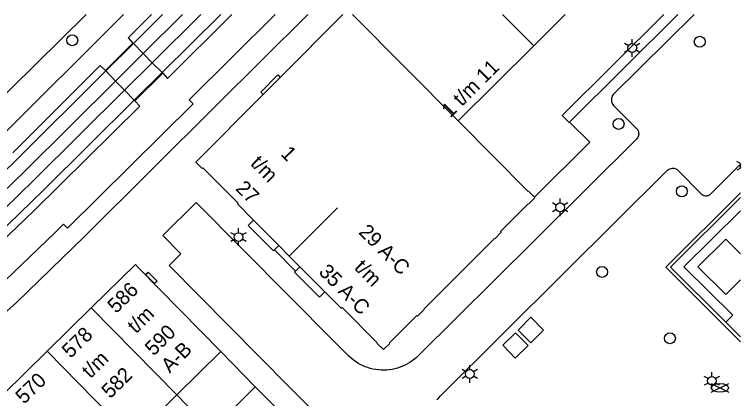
# Model space of a CAD drawing. Extents: x 122462 to 123306, y 485548 to 486417.
# Drawn here: x 123231.7 to 123306, y 486377.7 to 486417 of the extents above; entities that cross this region are included whole.
import ezdxf

# ---------------------------------------------------------------- set-up
doc = ezdxf.new("R2010")
doc.units = 0
for name, color, linetype in [('B-WE-IE-MEUBILAIR_WEGMEUBILAIR_VERKEERSBORD-S', 7, 'Continuous'), ('Level 1', 7, 'Continuous'), ('Level 17', 7, 'Continuous'), ('Level 19', 7, 'Continuous'), ('Level 21', 7, 'Continuous'), ('Level 30', 7, 'Continuous'), ('Level 31', 7, 'Continuous'), ('Level 37', 7, 'Continuous'), ('Level 4', 7, 'Continuous'), ('Level 40', 7, 'Continuous'), ('Level 42', 7, 'Continuous'), ('Level 50', 7, 'Continuous'), ('Level 52', 7, 'Continuous'), ('Level 53', 7, 'Continuous'), ('N-WE-AL-T25', 7, 'Continuous')]:
    doc.layers.add(name, color=color, linetype=linetype)

msp = doc.modelspace()

# ---------------------------------------------------------------- linework, layer by layer
at = {"layer": 'Level 1'}
for p, q in [((123284.843, 486413.759), (123288.06, 486416.958)), ((123277.113, 486406.073), (123284.843, 486413.759)), ((123258.889, 486410.532), (123257.139, 486408.777)), ((123256.156, 486395.927), (123258.75, 486393.326)), ((123258.75, 486393.326), (123259.824, 486392.249)), ((123259.824, 486392.249), (123260.91, 486391.16)), ((123260.91, 486391.16), (123263.474, 486388.589)), ((123239.549, 486386.962), (123235.039, 486382.526)), ((123235.039, 486382.526), (123230.529, 486378.09)), ((123248.312, 486378.054), (123252.82, 486382.489)), ((123256.34, 486378.88), (123251.87, 486374.438)), ((123243.802, 486373.618), (123248.312, 486378.054))]:
    msp.add_line(p, q, dxfattribs=at)
for points in [[(123265.299, 486416.958), (123258.889, 486410.532)], [(123257.139, 486408.777), (123250.249, 486401.87), (123250.899, 486401.219), (123250.964, 486401.284), (123254.589, 486397.659), (123254.509, 486397.579), (123256.156, 486395.927)], [(123284.912, 486398.276), (123284.299, 486398.889), (123284.269, 486398.859), (123277.113, 486406.073)], [(123263.474, 486388.589), (123265.14, 486386.92), (123265.219, 486386.999), (123268.834, 486383.364), (123268.799, 486383.329), (123269.479, 486382.679), (123270.122, 486383.325), (123270.087, 486383.36), (123272.893, 486386.175), (123272.964, 486386.105), (123273.627, 486386.77), (123273.592, 486386.806), (123280.821, 486394.057), (123280.856, 486394.022), (123281.528, 486394.696), (123281.457, 486394.766), (123284.264, 486397.583), (123284.3, 486397.547), (123284.969, 486398.219), (123284.912, 486398.276)], [(123252.82, 486382.489), (123244.419, 486391.01), (123244.059, 486391.4), (123239.549, 486386.962)], [(123260.294, 486374.764), (123260.37, 486374.84), (123256.34, 486378.88)]]:
    msp.add_lwpolyline(points, dxfattribs=at)
at = {"layer": 'Level 17'}
for p, q in [((123240.99, 486411.226), (123243.8, 486414.039)), ((123243.8, 486414.039), (123243.853, 486413.985)), ((123243.853, 486413.985), (123244.868, 486412.963)), ((123244.868, 486412.963), (123245.79, 486412.034)), ((123245.79, 486412.034), (123246.804, 486411.012)), ((123241.03, 486411.185), (123240.99, 486411.226)), ((123242.034, 486410.153), (123241.03, 486411.185)), ((123246.86, 486410.956), (123244.012, 486408.121)), ((123246.804, 486411.012), (123246.86, 486410.956)), ((123242.948, 486409.215), (123242.034, 486410.153)), ((123243.952, 486408.183), (123242.948, 486409.215)), ((123244.012, 486408.121), (123243.952, 486408.183)), ((123256.34, 486378.88), (123252.82, 486382.489))]:
    msp.add_line(p, q, dxfattribs=at)
for points in [[(123132.782, 486338.745), (123187.402, 486372.258), (123191.877, 486375.508), (123203.236, 486384.06), (123214.862, 486393.723), (123221.004, 486399.216), (123239.035, 486416.958)], [(123229.829, 486404.042), (123242.851, 486416.958)], [(123261.714, 486416.958), (123252.378, 486407.697), (123238.903, 486394.288), (123231.88, 486387.504), (123230.608, 486386.337)], [(123258.366, 486416.958), (123249.562, 486408.238), (123249.964, 486407.821), (123237.126, 486395.096), (123236.698, 486395.52), (123235.817, 486394.627), (123230.74, 486389.75)], [(123245.72, 486416.958), (123243.315, 486414.576), (123243.8, 486414.039)], [(123301.272, 486416.958), (123292.972, 486408.772), (123292.913, 486408.681), (123292.866, 486408.583), (123292.83, 486408.48), (123292.808, 486408.373), (123292.799, 486408.265), (123292.803, 486408.156), (123292.82, 486408.049), (123292.85, 486407.944), (123292.892, 486407.844), (123292.947, 486407.75), (123293.012, 486407.663), (123295.35, 486405.348), (123295.423, 486405.267), (123295.485, 486405.177), (123295.534, 486405.079), (123295.568, 486404.975), (123295.589, 486404.868), (123295.594, 486404.759), (123295.584, 486404.65), (123295.56, 486404.544), (123295.521, 486404.441), (123295.468, 486404.346), (123295.403, 486404.258), (123284.881, 486393.795), (123273.051, 486382.086), (123272.847, 486381.891), (123272.633, 486381.708), (123272.409, 486381.538), (123272.176, 486381.38), (123271.934, 486381.235), (123271.685, 486381.103), (123271.429, 486380.986), (123271.167, 486380.883), (123270.899, 486380.795), (123270.627, 486380.722), (123270.351, 486380.664), (123270.073, 486380.622), (123269.792, 486380.595), (123269.511, 486380.583), (123269.229, 486380.588), (123268.948, 486380.607), (123268.669, 486380.643), (123268.392, 486380.694), (123268.118, 486380.76), (123267.848, 486380.841), (123267.583, 486380.938), (123267.324, 486381.048), (123267.072, 486381.173), (123266.827, 486381.312), (123266.59, 486381.464), (123266.361, 486381.629), (123266.143, 486381.807), (123265.934, 486381.996), (123264.449, 486383.487), (123250.278, 486397.744), (123246.859, 486394.346), (123248.724, 486392.471), (123247.523, 486391.288), (123259.825, 486378.875), (123279.976, 486358.552)], [(123246.86, 486410.956), (123247.359, 486410.431), (123253.941, 486416.958)], [(123288.513, 486405.958), (123288.471, 486405.917), (123287.773, 486406.643), (123298.175, 486416.958)], [(123299.59, 486416.958), (123288.513, 486405.958)], [(123240.99, 486411.226), (123240.448, 486411.733), (123231.513, 486402.822)], [(123244.012, 486408.121), (123244.517, 486407.596), (123233.643, 486396.861), (123226.958, 486390.473)], [(123288.513, 486405.958), (123290.599, 486403.907), (123284.912, 486398.276)], [(123302.816, 486398.5), (123302.906, 486398.555), (123302.986, 486398.621), (123306.018, 486401.636)], [(123274.946, 486377.556), (123275.116, 486377.766), (123275.298, 486377.967), (123287.951, 486390.549), (123298.556, 486401.025), (123298.633, 486401.091), (123298.719, 486401.147), (123298.811, 486401.191), (123298.908, 486401.222), (123299.009, 486401.239), (123299.111, 486401.244), (123299.212, 486401.234), (123299.312, 486401.212), (123299.407, 486401.176), (123299.497, 486401.128), (123299.58, 486401.068), (123299.654, 486400.998), (123301.951, 486398.643), (123302.029, 486398.573), (123302.115, 486398.515), (123302.209, 486398.47), (123302.309, 486398.439), (123302.412, 486398.422), (123302.516, 486398.419), (123302.62, 486398.432), (123302.721, 486398.459), (123302.816, 486398.5)], [(123304.506, 486385.485), (123305.231, 486386.2), (123300.228, 486391.147), (123306.018, 486396.883)], [(123304.51, 486388.326), (123301.652, 486391.151), (123304.519, 486393.995), (123306.018, 486392.484)], [(123306.018, 486389.827), (123304.51, 486388.326)]]:
    msp.add_lwpolyline(points, dxfattribs=at)
at = {"layer": 'Level 19'}
msp.add_line((123251.87, 486374.438), (123248.312, 486378.054), dxfattribs=at)
at = {"layer": 'Level 21'}
for points in [[(123306.018, 486383.48), (123298.363, 486391.128), (123306.018, 486398.722)], [(123304.506, 486385.485), (123298.859, 486391.127), (123306.018, 486398.228)], [(123306.018, 486383.975), (123304.506, 486385.485)]]:
    msp.add_lwpolyline(points, dxfattribs=at)
at = {"layer": 'Level 30'}
for p, q in [((123258.75, 486393.326), (123258.295, 486392.874)), ((123260.455, 486390.707), (123260.91, 486391.16))]:
    msp.add_line(p, q, dxfattribs=at)
for points in [[(123257.139, 486408.777), (123256.891, 486409.024), (123258.641, 486410.779), (123258.889, 486410.532)], [(123258.295, 486392.874), (123258.192, 486392.771), (123255.599, 486395.371), (123256.156, 486395.927)], [(123263.474, 486388.589), (123262.917, 486388.034), (123260.353, 486390.605), (123260.455, 486390.707)]]:
    msp.add_lwpolyline(points, dxfattribs=at)
at = {"layer": 'Level 31'}
msp.add_line((123260.455, 486390.707), (123258.295, 486392.874), dxfattribs=at)
at = {"layer": 'Level 37'}
for p, q in [((123246.85, 486416.958), (123243.853, 486413.985)), ((123248.896, 486416.958), (123244.868, 486412.963)), ((123250.754, 486416.958), (123245.79, 486412.034)), ((123252.799, 486416.958), (123246.804, 486411.012)), ((123243.853, 486413.985), (123241.03, 486411.185)), ((123244.868, 486412.963), (123242.034, 486410.153)), ((123245.79, 486412.034), (123242.948, 486409.215)), ((123246.804, 486411.012), (123243.952, 486408.183))]:
    msp.add_line(p, q, dxfattribs=at)
for points in [[(123241.03, 486411.185), (123231.744, 486401.974), (123225.952, 486396.381), (123222.721, 486393.366), (123219.946, 486390.881), (123216.94, 486388.248), (123213.765, 486385.527), (123210.569, 486382.869), (123207.368, 486380.288), (123204.076, 486377.707), (123200.759, 486375.175), (123197.416, 486372.695), (123193.966, 486370.217), (123190.616, 486367.88), (123184.983, 486364.082), (123156.102, 486345.165)], [(123242.034, 486410.153), (123232.751, 486400.945), (123226.939, 486395.332), (123223.692, 486392.302), (123220.904, 486389.806), (123217.883, 486387.161), (123214.693, 486384.426), (123211.482, 486381.755), (123208.265, 486379.161), (123204.957, 486376.568), (123201.624, 486374.024), (123198.265, 486371.533), (123194.8, 486369.043), (123191.437, 486366.696), (123185.777, 486362.88), (123156.905, 486343.969)], [(123242.948, 486409.215), (123233.663, 486400.005), (123227.574, 486394.133), (123224.193, 486390.984), (123221.287, 486388.391), (123218.124, 486385.639), (123214.783, 486382.796), (123211.462, 486380.052), (123208.135, 486377.388), (123204.717, 486374.728), (123201.271, 486372.12), (123198.042, 486369.744), (123194.714, 486367.37), (123191.238, 486364.965), (123186.373, 486361.706), (123157.637, 486342.879)], [(123243.952, 486408.183), (123234.67, 486398.976), (123228.56, 486393.083), (123225.163, 486389.918), (123222.242, 486387.313), (123219.064, 486384.548), (123215.707, 486381.691), (123212.37, 486378.935), (123209.028, 486376.258), (123205.594, 486373.586), (123202.132, 486370.966), (123198.888, 486368.578), (123195.543, 486366.192), (123192.054, 486363.778), (123187.166, 486360.503), (123158.44, 486341.683)]]:
    msp.add_lwpolyline(points, dxfattribs=at)
at = {"layer": 'Level 4'}
for p, q in [((123277.113, 486406.073), (123266.308, 486416.958)), ((123284.843, 486413.759), (123281.664, 486416.958)), ((123248.312, 486378.054), (123239.549, 486386.962)), ((123243.802, 486373.618), (123235.039, 486382.526))]:
    msp.add_line(p, q, dxfattribs=at)
at = {"layer": 'Level 40'}
msp.add_lwpolyline([(123246.028, 486389.442), (123245.114, 486390.367), (123245.363, 486390.613), (123246.277, 486389.688), (123246.028, 486389.442)], dxfattribs=at)
at = {"layer": 'Level 42'}
for points in [[(123284.561, 486383.366), (123283.252, 486384.675), (123284.564, 486385.988), (123285.857, 486384.678), (123284.561, 486383.366)], [(123282.961, 486381.805), (123281.68, 486383.123), (123282.987, 486384.396), (123284.278, 486383.09), (123282.961, 486381.805)]]:
    msp.add_lwpolyline(points, dxfattribs=at)
at = {"layer": 'Level 50'}
for p, q in [((123294.939, 486413.986), (123294.939, 486414.436)), ((123294.549, 486413.761), (123294.159, 486413.986)), ((123295.718, 486413.986), (123295.328, 486413.761)), ((123294.549, 486413.311), (123294.159, 486413.086)), ((123294.939, 486412.636), (123294.939, 486413.086)), ((123295.718, 486413.086), (123295.328, 486413.311)), ((123306.018, 486401.704), (123305.638, 486401.923)), ((123306.018, 486401.266), (123306.018, 486401.679)), ((123306.018, 486401.242), (123305.638, 486401.023)), ((123287.55, 486397.683), (123287.55, 486398.133)), ((123287.16, 486397.458), (123286.77, 486397.683)), ((123288.329, 486397.683), (123287.939, 486397.458)), ((123287.16, 486397.008), (123286.77, 486396.783)), ((123287.55, 486396.333), (123287.55, 486396.783)), ((123288.329, 486396.783), (123287.939, 486397.008)), ((123254.621, 486394.644), (123254.621, 486395.094)), ((123254.231, 486394.419), (123253.841, 486394.644)), ((123255.4, 486394.644), (123255.01, 486394.419)), ((123254.231, 486393.969), (123253.841, 486393.744)), ((123254.621, 486393.294), (123254.621, 486393.744)), ((123255.4, 486393.744), (123255.01, 486393.969)), ((123278.3, 486380.64), (123278.3, 486381.09)), ((123277.91, 486380.415), (123277.52, 486380.64)), ((123277.91, 486379.965), (123277.52, 486379.74)), ((123279.079, 486380.64), (123278.689, 486380.415)), ((123279.079, 486379.74), (123278.689, 486379.965)), ((123303.087, 486379.94), (123303.087, 486380.39)), ((123278.3, 486379.29), (123278.3, 486379.74)), ((123302.697, 486379.715), (123302.307, 486379.94)), ((123302.697, 486379.265), (123302.307, 486379.04)), ((123303.866, 486379.94), (123303.476, 486379.715)), ((123303.866, 486379.04), (123303.476, 486379.265)), ((123303.087, 486378.59), (123303.087, 486379.04))]:
    msp.add_line(p, q, dxfattribs=at)
for centre in [(123294.939, 486413.536), (123287.55, 486397.233), (123254.621, 486394.194), (123278.3, 486380.19), (123303.087, 486379.49)]:
    msp.add_circle(centre, 0.45, dxfattribs=at)
msp.add_arc((123306.418, 486401.473), 0.45, 152.66352, 207.33648, dxfattribs=at)
at = {"layer": 'Level 52'}
for p, q in [((123303.028, 486378.321), (123304.809, 486379.211)), ((123303.028, 486379.211), (123304.809, 486378.321))]:
    msp.add_line(p, q, dxfattribs=at)
msp.add_ellipse((123303.918, 486378.764), major_axis=(0.89, 0), ratio=0.5, dxfattribs=at)
at = {"layer": 'Level 53'}
for centre in [(123237.6, 486414.325), (123301.844, 486414.175), (123293.537, 486405.772), (123300.012, 486398.869), (123291.851, 486390.629), (123298.794, 486383.843)]:
    msp.add_circle(centre, 0.56, dxfattribs=at)
at = {"layer": 'N-WE-AL-T25'}
msp.add_line((123259.824, 486392.249), (123264.767, 486397.178), dxfattribs=at)

# ---------------------------------------------------------------- texts
at = {"layer": 'B-WE-IE-MEUBILAIR_WEGMEUBILAIR_VERKEERSBORD-S'}
for s, rotation, p in [('1 t/m 11', 44.84086, (123276.296, 486406.316)), ('1', 314.91926, (123258.862, 486402.626)), ('t/m', 314.91926, (123255.757, 486401.647)), ('27', 314.91926, (123254.24, 486399.075)), ('29 A-C', 314.91926, (123266.847, 486394.619)), ('35 A-C', 314.91926, (123262.753, 486390.537)), ('t/m', 314.91926, (123266.387, 486390.987)), ('586', 44.52991, (123242.096, 486386.313)), ('t/m', 44.52991, (123244.123, 486384.252)), ('590', 44.52991, (123245.924, 486381.969)), ('578', 44.52991, (123237.432, 486381.725)), ('A-B', 44.52991, (123247.585, 486380.222)), ('t/m', 44.52991, (123239.459, 486379.664)), ('582', 44.52991, (123241.486, 486377.603)), ('570', 44.52991, (123232.671, 486377.041))]:
    msp.add_text(s, height=1.5, rotation=rotation, dxfattribs=at).set_placement(p)

doc.saveas('drawing.dxf')
